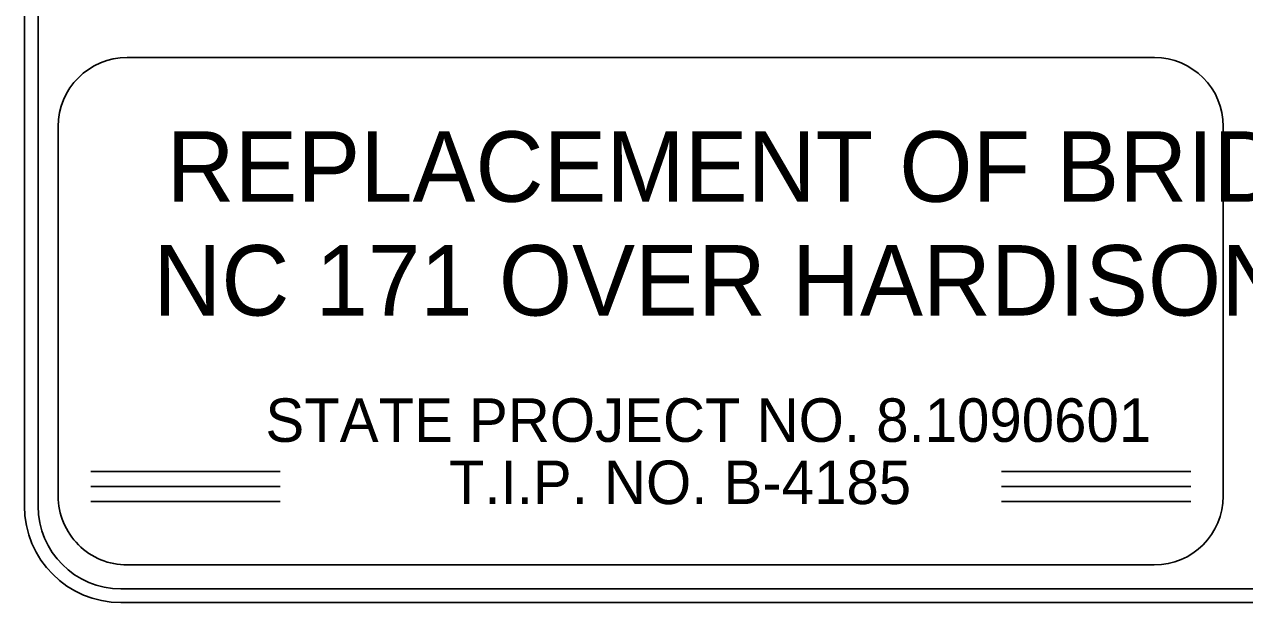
# Model space of a CAD drawing. Extents: x 2598976 to 2600165, y 728604 to 730243.
# Drawn here: x 2598980.7 to 2599361.3, y 728645.5 to 728825.9 of the extents above; entities that cross this region are included whole.
import ezdxf

# ---------------------------------------------------------------- set-up
doc = ezdxf.new("R2010")
doc.units = 0
doc.layers.add('Old_Level_63', color=7, linetype='Continuous')

msp = doc.modelspace()

# ---------------------------------------------------------------- linework, layer by layer
at = {"layer": 'Old_Level_63'}
for p, q in [((2598980.71, 728675.66), (2598980.71, 730208.07)), ((2598980.71, 728675.66), (2598980.71, 730208.07)), ((2598980.71, 728675.66), (2598980.71, 730208.07)), ((2598985.01, 728674.53), (2598985.01, 730208.54)), ((2598985.01, 728674.53), (2598985.01, 730208.54)), ((2598985.01, 728674.53), (2598985.01, 730208.54)), ((2599333.16, 728815.55), (2599012.77, 728815.55)), ((2599333.16, 728815.55), (2599012.77, 728815.55)), ((2599333.16, 728815.55), (2599012.77, 728815.55)), ((2598991.28, 728678.78), (2598991.28, 728794.04)), ((2598991.28, 728678.78), (2598991.28, 728794.04)), ((2598991.28, 728678.78), (2598991.28, 728794.04)), ((2599354.66, 728678.78), (2599354.66, 728794.04)), ((2599354.66, 728678.78), (2599354.66, 728794.04)), ((2599354.66, 728678.78), (2599354.66, 728794.04)), ((2599333.15, 728657.27), (2599012.79, 728657.27)), ((2599333.15, 728657.27), (2599012.79, 728657.27)), ((2599333.15, 728657.27), (2599012.79, 728657.27)), ((2599010.83, 728649.84), (2599994.19, 728649.84)), ((2599010.83, 728649.84), (2599994.19, 728649.84)), ((2599010.83, 728649.84), (2599994.19, 728649.84)), ((2599010.83, 728645.54), (2599994.19, 728645.54)), ((2599010.83, 728645.54), (2599994.19, 728645.54)), ((2599010.83, 728645.54), (2599994.19, 728645.54))]:
    msp.add_line(p, q, dxfattribs=at)
for points in [[(2599001.41, 728686.42), (2599060.47, 728686.42)], [(2599001.41, 728686.42), (2599060.47, 728686.42)], [(2599001.41, 728686.42), (2599060.47, 728686.42)], [(2599285.47, 728686.42), (2599344.53, 728686.42)], [(2599285.47, 728686.42), (2599344.53, 728686.42)], [(2599285.47, 728686.42), (2599344.53, 728686.42)], [(2599001.41, 728681.74), (2599060.47, 728681.74)], [(2599001.41, 728681.74), (2599060.47, 728681.74)], [(2599001.41, 728681.74), (2599060.47, 728681.74)], [(2599285.47, 728681.74), (2599344.53, 728681.74)], [(2599285.47, 728681.74), (2599344.53, 728681.74)], [(2599285.47, 728681.74), (2599344.53, 728681.74)], [(2599001.41, 728677.06), (2599060.47, 728677.06)], [(2599001.41, 728677.06), (2599060.47, 728677.06)], [(2599001.41, 728677.06), (2599060.47, 728677.06)], [(2599285.47, 728677.06), (2599344.53, 728677.06)], [(2599285.47, 728677.06), (2599344.53, 728677.06)], [(2599285.47, 728677.06), (2599344.53, 728677.06)]]:
    msp.add_lwpolyline(points, dxfattribs=at)
for radius in [30.12, 30.12, 30.12, 25.84, 25.84, 25.84]:
    msp.add_arc((2599010.83, 728675.66), radius, 180, 270, dxfattribs=at)
for centre, major_axis, start_param, end_param in [((2599012.77, 728794.04), (0, 21.51), 0, 1.570796), ((2599012.77, 728794.04), (0, 21.51), 0, 1.570796), ((2599012.77, 728794.04), (0, 21.51), 0, 1.570796), ((2599333.16, 728794.04), (0, 21.51), 4.712389, 6.283185), ((2599333.16, 728794.04), (0, 21.51), 4.712389, 6.283185), ((2599333.16, 728794.04), (0, 21.51), 4.712389, 6.283185), ((2599012.79, 728678.8), (0, -21.53), 4.712387, 6.283185), ((2599012.79, 728678.8), (0, -21.53), 4.712387, 6.283185), ((2599012.79, 728678.8), (0, -21.53), 4.712387, 6.283185), ((2599333.15, 728678.78), (0, 21.51), 3.141593, 4.712389), ((2599333.15, 728678.78), (0, 21.51), 3.141593, 4.712389), ((2599333.15, 728678.78), (0, 21.51), 3.141593, 4.712389)]:
    msp.add_ellipse(centre, major_axis=major_axis, ratio=0.999998, start_param=start_param, end_param=end_param, dxfattribs=at)

# ---------------------------------------------------------------- texts
for s, height, p in [('REPLACEMENT OF BRIDGE NO. 16 ON', 21.9724, (2599025.04, 728770.57)), ('NC 171 OVER HARDISON MILL CREEK', 21.9724, (2599020.92, 728735.08)), ('STATE PROJECT NO. 8.1090601', 13.5671, (2599055.89, 728695.68)), ('T.I.P. NO. B-4185', 13.5671, (2599113.11, 728676.27))]:
    msp.add_text(s, height=height, dxfattribs=at).set_placement(p)

doc.saveas('drawing.dxf')
